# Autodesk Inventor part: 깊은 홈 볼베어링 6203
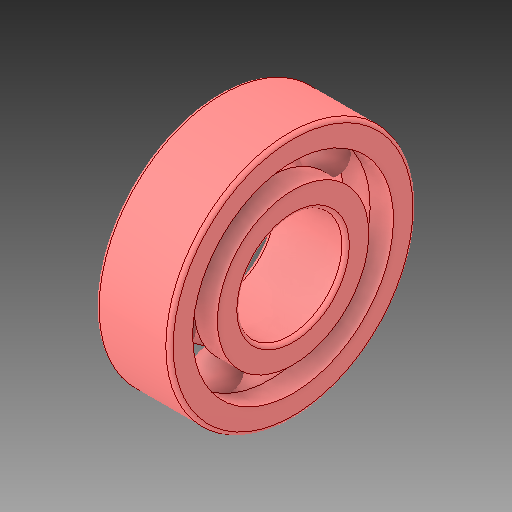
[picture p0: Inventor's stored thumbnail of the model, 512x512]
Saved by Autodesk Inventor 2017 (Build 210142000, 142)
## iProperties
Created: 2024-09
Part Number: 깊은 홈 볼베어링 6203
Material: 일반
Description: 깊은 그루브 볼 베어링
Document SubType Name: Modeling
Designer: MRC
Density: 1 g/cm^3
Appearance: 기본값
Author: jhkim
Sending System: Autodesk Inventor 2025
Preprocessor: ST-DEVELOPER v20
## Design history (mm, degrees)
feature "Solid1"
feature "Solid1:1"
feature "Solid1:2"
feature "Solid1:3"
feature "Solid1:4"
feature "Solid1:5"
feature "Solid1:6"
feature "Solid1:7"
feature "Solid1:8"
node "솔리드1"
node "솔리드2"
node "솔리드3"
node "솔리드4"
node "솔리드5"
node "솔리드6"
node "솔리드7"
node "솔리드8"
node "솔리드9"
